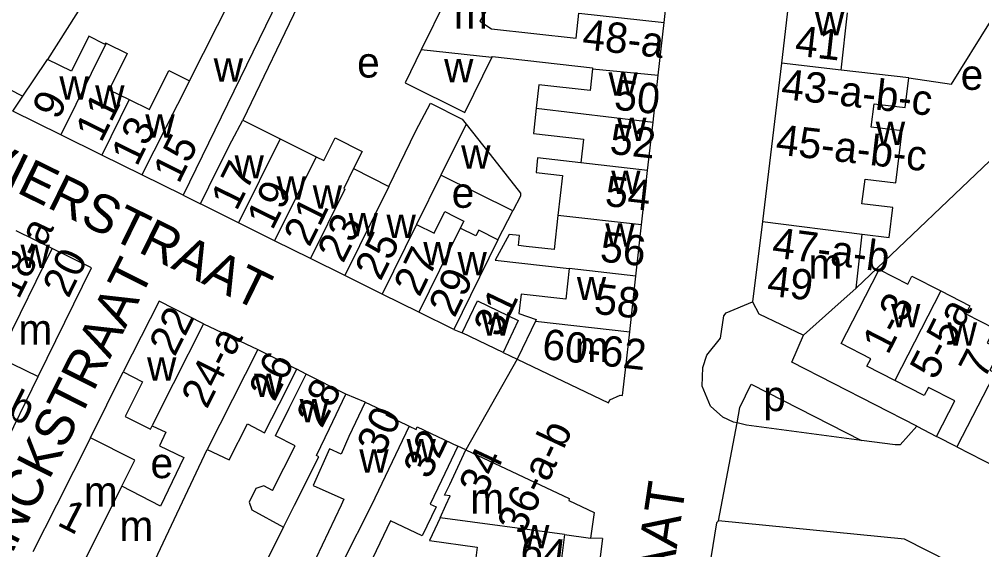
# Model space of a CAD drawing. Extents: x 159700 to 161346, y 381730 to 382922.
# Drawn here: x 160801.9 to 160928.7, y 382427.4 to 382497.3 of the extents above; entities that cross this region are included whole.
import ezdxf

# ---------------------------------------------------------------- set-up
doc = ezdxf.new("R2010")
doc.units = 0
for name, color, linetype in [('BLT_Basislijn', 7, 'Continuous'), ('BLT_Bebouwing', 7, 'Continuous'), ('BLT_Centroide', 7, 'Continuous'), ('BLT_Huisnummer', 7, 'Continuous'), ('BLT_Huisnummer_ tussenligend', 7, 'Continuous'), ('BLT_Huisnummer_reeks', 7, 'Continuous'), ('BLT_Onderverdeling_panden', 7, 'Continuous'), ('BLT_Straatnaam', 7, 'Continuous'), ('BLT_Vlakafsluiter', 7, 'Continuous')]:
    doc.layers.add(name, color=color, linetype=linetype)

msp = doc.modelspace()

# ---------------------------------------------------------------- linework, layer by layer
at = {"layer": 'BLT_Basislijn'}
for p, q in [((160844.01, 382510.3), (160831.41, 382483.99)), ((160812.33, 382502.56), (160805.67, 382492.01)), ((160932.23, 382481.02), (160912.18, 382461.91)), ((160823.53, 382474.14), (160825.81, 382472.98)), ((160864.97, 382468.25), (160866.94, 382472.07)), ((160859.17, 382456.45), (160860.27, 382456.02)), ((160865.66, 382453.44), (160867.54, 382452.56)), ((160811.34, 382442.2), (160815.64, 382450.86)), ((160839.75, 382450.55), (160838.49, 382451.23)), ((160847.5, 382446.87), (160844.97, 382447.93)), ((160920.15, 382443.72), (160922.75, 382442.38)), ((160860.76, 382440.59), (160859.71, 382441.07)), ((160878.75, 382428.94), (160877.18, 382428.98))]:
    msp.add_line(p, q, dxfattribs=at)
for points in [[(160919.1, 382489.6), (160924.73, 382488.77), (160929.87, 382497)], [(160794.98, 382490.95), (160802.41, 382487.16)], [(160925.44, 382441), (160942.54, 382432.23), (160952.75, 382453.52), (160968.62, 382484.37)], [(160896.49, 382444.14), (160896.04, 382444.25), (160894.62, 382444.9), (160892.99, 382446.35), (160891.89, 382449), (160892, 382451.44), (160892.51, 382453.08), (160894.31, 382455.31), (160894.74, 382458.24), (160895.06, 382458.63), (160898.5, 382460.08)], [(160920.15, 382443.72), (160903.69, 382452.14), (160905.24, 382455.7)], [(160896.49, 382444.14), (160896.84, 382446.18), (160898.34, 382449.26), (160912.86, 382441.83)], [(160912.86, 382441.83), (160897.72, 382443.85), (160896.49, 382444.14)], [(160920.15, 382443.72), (160917.96, 382441.28), (160917.32, 382441.24), (160912.86, 382441.83)], [(160836.75, 382430.42), (160831.89, 382420.74), (160827.5, 382410.41)], [(160894.04, 382431.25), (160893.79, 382430.98), (160889.78, 382406.32), (160889.59, 382405.97), (160888.44, 382398.41), (160886.23, 382386.3), (160880.39, 382363.74), (160877.82, 382356.02), (160875.07, 382349.91), (160874.64, 382347.73), (160873.08, 382344.09), (160872.77, 382343.42)], [(160930.49, 382422.78), (160918.54, 382428.86), (160894.04, 382431.25)], [(160878.75, 382428.94), (160877.31, 382417.57), (160876.53, 382411.48), (160874.58, 382396.07), (160872.75, 382388.17), (160871.43, 382382.42), (160870.23, 382377.23), (160868.92, 382371.56), (160868.07, 382367.85), (160866.97, 382363.08)]]:
    msp.add_lwpolyline(points, dxfattribs=at)
at = {"layer": 'BLT_Bebouwing'}
for p, q in [((160858.17, 382500), (160854.89, 382493.28)), ((160886.88, 382496.85), (160887.22, 382500.01)), ((160903.22, 382499.11), (160902.35, 382491.51)), ((160910.19, 382490.61), (160911.05, 382498.13)), ((160886.11, 382489.94), (160886.88, 382496.85)), ((160902.35, 382491.51), (160899.82, 382470.68)), ((160885.42, 382483.75), (160886.11, 382489.94)), ((160919.1, 382489.6), (160910.19, 382490.61)), ((160884.71, 382477.4), (160885.42, 382483.75)), ((160860.81, 382483.48), (160864.44, 382478.86)), ((160812.84, 382479.4), (160807.42, 382482.07)), ((160818.1, 382476.81), (160812.84, 382479.4)), ((160845.98, 382477.63), (160850.61, 382475.28)), ((160883.91, 382470.21), (160884.71, 382477.4)), ((160823.53, 382474.14), (160818.1, 382476.81)), ((160857.48, 382476.77), (160854.27, 382470.28)), ((160866.94, 382472.07), (160857.48, 382476.77)), ((160873.49, 382476.72), (160872.9, 382471.45)), ((160830.81, 382470.5), (160825.81, 382472.98)), ((160835.57, 382468.14), (160830.81, 382470.5)), ((160883.16, 382463.48), (160883.91, 382470.21)), ((160899.82, 382470.68), (160898.5, 382460.08)), ((160806.29, 382467.11), (160801.54, 382469.44)), ((160912.18, 382461.91), (160912.97, 382469.02)), ((160840.29, 382465.81), (160835.57, 382468.14)), ((160844.84, 382463.55), (160840.29, 382465.81)), ((160849.74, 382461.12), (160844.84, 382463.55)), ((160882.99, 382461.87), (160883.16, 382463.48)), ((160854.56, 382458.74), (160849.74, 382461.12)), ((160882.35, 382456.16), (160882.99, 382461.87)), ((160859.17, 382456.45), (160854.56, 382458.74)), ((160826.19, 382457.2), (160833.37, 382453.82)), ((160865.66, 382453.44), (160860.27, 382456.02)), ((160881.79, 382451.15), (160882.35, 382456.16)), ((160833.37, 382453.82), (160838.49, 382451.23)), ((160867.61, 382452.73), (160867.54, 382452.56)), ((160844.97, 382447.93), (160839.75, 382450.55)), ((160817.17, 382439.24), (160811.34, 382442.2)), ((160925.44, 382441), (160922.75, 382442.38)), ((160817.14, 382420.37), (160826.71, 382440.66)), ((160860.76, 382440.59), (160874.38, 382434.21)), ((160815.47, 382435.83), (160817.17, 382439.24)), ((160873.78, 382429.47), (160873.03, 382423.58)), ((160873.78, 382429.47), (160877.18, 382428.98))]:
    msp.add_line(p, q, dxfattribs=at)
for points in [[(160824.37, 382489.21), (160831.76, 382503.82), (160822.54, 382508.46), (160825.78, 382513.72)], [(160836.89, 382501.55), (160823.53, 382474.14)], [(160813.37, 382494.16), (160813.17, 382494.02), (160811.09, 382495.05), (160808.83, 382490.46), (160805.67, 382492.01)], [(160813.37, 382494.16), (160816.14, 382492.8), (160813.78, 382488.02), (160816.44, 382486.71)], [(160854.89, 382493.28), (160852.76, 382488.92), (160860.62, 382485.03), (160864.19, 382492.24)], [(160864.19, 382492.24), (160864.26, 382492.39), (160877.46, 382490.9), (160877.45, 382490.77)], [(160802.41, 382487.16), (160803.88, 382489.34), (160805.67, 382492.01)], [(160816.44, 382486.71), (160819.1, 382485.4), (160821.64, 382490.55), (160824.37, 382489.21)], [(160877.45, 382490.77), (160877.13, 382487.9), (160870.37, 382488.65), (160870.03, 382485.57)], [(160912.97, 382469.02), (160916.53, 382468.57), (160917.01, 382472.5), (160912.94, 382472.98), (160913.34, 382476.24), (160917.41, 382475.75), (160918.24, 382482.61), (160914.17, 382483.1), (160914.54, 382486.18), (160918.62, 382485.68), (160919.1, 382489.6)], [(160807.42, 382482.07), (160801.09, 382485.19), (160802.41, 382487.16)], [(160850.61, 382475.28), (160854.19, 382482.6), (160856.13, 382486.25), (160860.28, 382484.15), (160860.81, 382483.48)], [(160870.03, 382485.57), (160869.66, 382482.26), (160876.26, 382481.53), (160875.91, 382478.39)], [(160825.81, 382472.98), (160828.03, 382477.46), (160829.96, 382481.29), (160831.41, 382483.99)], [(160831.41, 382483.99), (160836.3, 382481.55)], [(160836.3, 382481.55), (160841.04, 382479.19)], [(160841.04, 382479.19), (160842.06, 382478.68), (160843.54, 382481.67)], [(160843.54, 382481.67), (160847.11, 382479.9), (160845.98, 382477.63)], [(160864.44, 382478.86), (160867.95, 382474.41), (160867.97, 382474.02), (160866.94, 382472.07)], [(160875.91, 382478.39), (160870.22, 382479.03), (160870.01, 382477.11), (160873.49, 382476.72)], [(160854.27, 382470.28), (160856.59, 382469.14), (160857.99, 382471.97), (160859.28, 382471.33)], [(160859.28, 382471.33), (160860.5, 382470.73), (160860.03, 382469.79)], [(160872.9, 382471.45), (160872.39, 382466.98), (160868.73, 382467.39), (160867.7, 382467.51), (160867.85, 382468.81), (160866.46, 382468.97), (160864.63, 382465.56), (160874.36, 382464.47)], [(160864.97, 382468.25), (160862.47, 382469.51), (160862.07, 382468.76), (160860.03, 382469.79)], [(160804.44, 382450.24), (160811.47, 382464.57), (160806.29, 382467.11)], [(160864.97, 382468.25), (160861.39, 382460.93), (160859.17, 382456.45)], [(160874.36, 382464.47), (160873.92, 382460.42), (160868.03, 382461.08), (160867.75, 382458.55), (160870.03, 382457.77), (160869.93, 382457.55)], [(160917.28, 382449.72), (160913.59, 382451.61), (160914.1, 382452.6), (160910.2, 382454.6), (160912.48, 382459.05), (160915.19, 382464.34)], [(160915.19, 382464.34), (160918.97, 382462.41), (160919.52, 382463.47), (160923.33, 382461.52)], [(160905.24, 382455.7), (160908.96, 382459.03), (160912.18, 382461.91)], [(160923.33, 382461.52), (160927.14, 382459.57), (160926.6, 382458.52), (160930.4, 382456.57), (160929.43, 382454.68), (160931.17, 382453.79), (160929.78, 382451.08), (160930.43, 382450.75), (160929.54, 382449), (160925.44, 382441)], [(160826.19, 382457.2), (160820.35, 382460.16), (160815.64, 382450.86)], [(160860.27, 382456.02), (160862.28, 382460.21), (160867.67, 382457.63), (160865.66, 382453.44)], [(160898.5, 382460.08), (160899.36, 382458.53), (160905.24, 382455.7)], [(160869.93, 382457.55), (160867.61, 382452.73)], [(160867.54, 382452.56), (160879.55, 382446.8), (160879.73, 382447.18), (160881.1, 382447.78), (160881.41, 382447.74), (160881.79, 382451.15)], [(160815.64, 382450.86), (160818.19, 382449.56), (160815.88, 382445), (160819.21, 382443.31), (160819.45, 382443.78)], [(160826.71, 382440.66), (160829.6, 382439.29), (160831.99, 382444.01), (160834.25, 382442.86), (160836.16, 382446.62), (160838.49, 382451.23)], [(160835.32, 382435.27), (160838.27, 382441.15), (160835.68, 382442.44), (160837.51, 382446.08), (160839.75, 382450.55)], [(160799.64, 382440.43), (160804.44, 382450.24)], [(160922.75, 382442.38), (160925.15, 382447.06), (160921.69, 382448.83), (160921.14, 382447.74), (160917.28, 382449.72)], [(160836.75, 382430.42), (160838.21, 382433.33), (160841.4, 382439.7), (160841.08, 382439.86), (160842.8, 382443.43), (160844.97, 382447.93)], [(160847.5, 382446.87), (160845.36, 382442.35), (160844.33, 382440.03), (160842.79, 382440.72), (160840.65, 382435.89), (160844.71, 382434.09), (160844.36, 382433.33), (160840.18, 382424.54), (160843.26, 382423.08)], [(160847.5, 382446.87), (160850.38, 382445.5), (160850.23, 382445.19), (160853.29, 382443.73)], [(160819.45, 382443.78), (160821.26, 382442.91), (160820.41, 382441.15), (160823.64, 382439.59), (160820.55, 382433.19), (160815.47, 382435.83)], [(160853.29, 382443.73), (160854.21, 382443.3), (160854.36, 382443.61), (160859.71, 382441.07)], [(160811.34, 382442.2), (160806.85, 382433.33), (160803.72, 382427.16)], [(160859.71, 382441.07), (160857.56, 382436.56), (160856.07, 382433.47), (160856.84, 382433.11), (160855.02, 382429.27), (160850.82, 382431.27), (160847.53, 382424.36), (160844.54, 382425.78)], [(160857.37, 382431.65), (160858.15, 382433.33), (160858.7, 382434.53), (160857.97, 382434.64), (160858.64, 382436.06), (160860.76, 382440.59)], [(160835.32, 382435.27), (160834.14, 382435.85), (160833.11, 382435.53), (160832.21, 382433.73), (160832.56, 382432.7), (160836.75, 382430.42)], [(160874.38, 382434.21), (160874.34, 382433.93), (160877.67, 382432.37), (160877.18, 382428.98)], [(160857.37, 382431.65), (160855.97, 382428.65), (160862.27, 382427.79), (160861.92, 382424.98), (160863.32, 382424.81)]]:
    msp.add_lwpolyline(points, dxfattribs=at)
at = {"layer": 'BLT_Onderverdeling_panden'}
for p, q in [((160813.37, 382494.16), (160807.42, 382482.07)), ((160864.19, 382492.24), (160854.89, 382493.28)), ((160910.19, 382490.61), (160902.35, 382491.51)), ((160877.45, 382490.77), (160886.11, 382489.94)), ((160824.37, 382489.21), (160818.1, 382476.81)), ((160816.44, 382486.71), (160812.84, 382479.4)), ((160870.03, 382485.57), (160885.42, 382483.75)), ((160860.81, 382483.48), (160857.48, 382476.77)), ((160836.3, 382481.55), (160830.81, 382470.5)), ((160841.04, 382479.19), (160835.57, 382468.14)), ((160884.71, 382477.4), (160875.91, 382478.39)), ((160850.61, 382475.28), (160844.84, 382463.55)), ((160883.91, 382470.21), (160872.9, 382471.45)), ((160854.27, 382470.28), (160849.74, 382461.12)), ((160860.03, 382469.79), (160854.56, 382458.74)), ((160899.82, 382470.68), (160912.97, 382469.02)), ((160800, 382454.28), (160806.29, 382467.11)), ((160883.16, 382463.48), (160874.36, 382464.47)), ((160923.33, 382461.52), (160917.28, 382449.72)), ((160869.93, 382457.55), (160882.35, 382456.16)), ((160833.37, 382453.82), (160826.71, 382440.66)), ((160799.26, 382452.77), (160804.44, 382450.24)), ((160820.21, 382445.3), (160819.45, 382443.78)), ((160809.63, 382424.17), (160815.47, 382435.83)), ((160873.78, 382429.47), (160857.37, 382431.65))]:
    msp.add_line(p, q, dxfattribs=at)
for points in [[(160859.63, 382502.61), (160864.48, 382500.21), (160862.62, 382497.04), (160864.15, 382496.03), (160875.29, 382494.8), (160875.65, 382498.11), (160886.88, 382496.85)], [(160845.98, 382477.63), (160844.68, 382475.01), (160844.81, 382474.94), (160840.29, 382465.81)], [(160826.19, 382457.2), (160822.22, 382449.31), (160820.21, 382445.3)], [(160853.29, 382443.73), (160848.34, 382433.33), (160844.54, 382425.78)]]:
    msp.add_lwpolyline(points, dxfattribs=at)
at = {"layer": 'BLT_Vlakafsluiter'}
for p, q in [((160867.54, 382452.56), (160860.76, 382440.59)), ((160894.04, 382431.25), (160896.49, 382444.14))]:
    msp.add_line(p, q, dxfattribs=at)

# ---------------------------------------------------------------- texts
at = {"layer": 'BLT_Centroide'}
for s, p in [('m', (160859.19, 382496.07)), ('w', (160906.75, 382495.19)), ('e', (160846.45, 382489.62)), ('w', (160827.55, 382489.08)), ('w', (160857.9, 382489.01)), ('e', (160925.94, 382488)), ('w', (160879.55, 382487.25)), ('w', (160807.23, 382486.7)), ('w', (160811.94, 382485.53)), ('w', (160818.55, 382481.69)), ('w', (160880.69, 382481.25)), ('w', (160914.76, 382480.72)), ('w', (160860.15, 382477.62)), ('w', (160830.3, 382476.33)), ('w', (160879.91, 382474.31)), ('w', (160835.84, 382473.53)), ('w', (160840.59, 382472.36)), ('e', (160858.9, 382472.47)), ('w', (160845.31, 382468.72)), ('w', (160850.31, 382468.48)), ('w', (160879.14, 382467.34)), ('w', (160802.11, 382464.53)), ('w', (160855.16, 382464.89)), ('w', (160859.66, 382463.57)), ('m', (160905.89, 382463.12)), ('w', (160875.38, 382460.31)), ('w', (160916.77, 382456.75)), ('w', (160862.83, 382455.65)), ('m', (160801.83, 382454.47)), ('w', (160924.22, 382454.3)), ('m', (160875.12, 382452.19)), ('w', (160818.77, 382449.72)), ('w', (160832.86, 382447.58)), ('p', (160899.93, 382445.7)), ('w', (160838.87, 382444.24)), ('w', (160852.95, 382438.97)), ('w', (160846.73, 382437.59)), ('e', (160819.23, 382436.87)), ('m', (160810.45, 382433.11)), ('m', (160861.35, 382432.22)), ('m', (160815.13, 382428.59)), ('w', (160867.9, 382427.62))]:
    msp.add_text(s, height=4, dxfattribs=at).set_placement(p)
at = {"layer": 'BLT_Huisnummer'}
for s, rotation, p in [('50', 353.6751, (160880.18, 382485.43)), ('11', 63.7726, (160812.74, 382480.92)), ('15', 63.645, (160822.95, 382475.51)), ('17', 63.6511, (160830.57, 382471.93)), ('54', 353.6761, (160878.97, 382472.74)), ('21', 63.6528, (160840.16, 382467.18)), ('25', 63.6475, (160849.53, 382462.71)), ('29', 64.3982, (160859.28, 382457.87)), ('58', 353.6761, (160877.54, 382458.54)), ('31', 64.3982, (160865.19, 382455.26)), ('22', 63.2725, (160822.42, 382452.75)), ('26', 63.2313, (160835.55, 382446.81)), ('7', 62.8881, (160929.04, 382449.74)), ('30', 64.2755, (160849.81, 382439.63)), ('1', 333.1275, (160806.79, 382430.75)), ('64', 352.774, (160867.77, 382425.5))]:
    msp.add_text(s, height=4, rotation=rotation, dxfattribs=at).set_placement(p)
at = {"layer": 'BLT_Huisnummer_ tussenligend'}
for s, rotation, p in [('41', 353.5586, (160904, 382492.53)), ('9', 63.7726, (160807.06, 382483.91)), ('13', 63.7726, (160817.44, 382477.79)), ('52', 353.6751, (160879.61, 382479.6)), ('19', 63.6511, (160835.29, 382469.39)), ('23', 63.6528, (160844.6, 382465.04)), ('56', 353.6761, (160878.32, 382465.42)), ('27', 63.6475, (160854.64, 382460.6)), ('28', 63.2313, (160841.81, 382443.32)), ('32', 64.2755, (160855.93, 382436.58))]:
    msp.add_text(s, height=4, rotation=rotation, dxfattribs=at).set_placement(p)
at = {"layer": 'BLT_Huisnummer_reeks'}
for s, rotation, p in [('48-a', 353.6664, (160875.99, 382493.37)), ('43-a-b-c', 353.5306, (160902.18, 382486.83)), ('45-a-b-c', 353.5306, (160901.47, 382479.52)), ('18-a', 63.8893, (160801.86, 382460.29)), ('47-a-b', 352.5129, (160900.97, 382465.97)), ('20', 63.8857, (160808.42, 382460.45)), ('49', 353.5306, (160900.33, 382460.92)), ('1-3', 62.8843, (160916.36, 382452.99)), ('5-5a', 62.8712, (160922.61, 382449.66)), ('24-a', 63.2725, (160826.65, 382445.87)), ('60-62', 353.6771, (160870.69, 382452.59)), ('2-a-b', 333.8911, (160791.55, 382449.26)), ('36-a-b', 64.8855, (160868.32, 382429.24)), ('34', 64.8855, (160863.28, 382434.24))]:
    msp.add_text(s, height=4, rotation=rotation, dxfattribs=at).set_placement(p)
at = {"layer": 'BLT_Straatnaam'}
for s, rotation, p in [('RIVIERSTRAAT', 333.8865, (160789.76, 382480.28)), ('LEDEGANCKSTRAAT', 63.2992, (160789.34, 382403.68)), ('GESTELSESTRAAT', 81.5437, (160880.72, 382374.94))]:
    msp.add_text(s, height=5, rotation=rotation, dxfattribs=at).set_placement(p)

doc.saveas('drawing.dxf')
